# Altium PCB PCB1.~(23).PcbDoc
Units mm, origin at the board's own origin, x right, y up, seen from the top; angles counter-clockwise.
Board outline 145.29 x 144.91 mm, 2 copper layers (Top Layer, Bottom Layer); 47 components, 43 nets, 244 pads, 0 vias.
Unrouted connection lines stored in the file: 137.
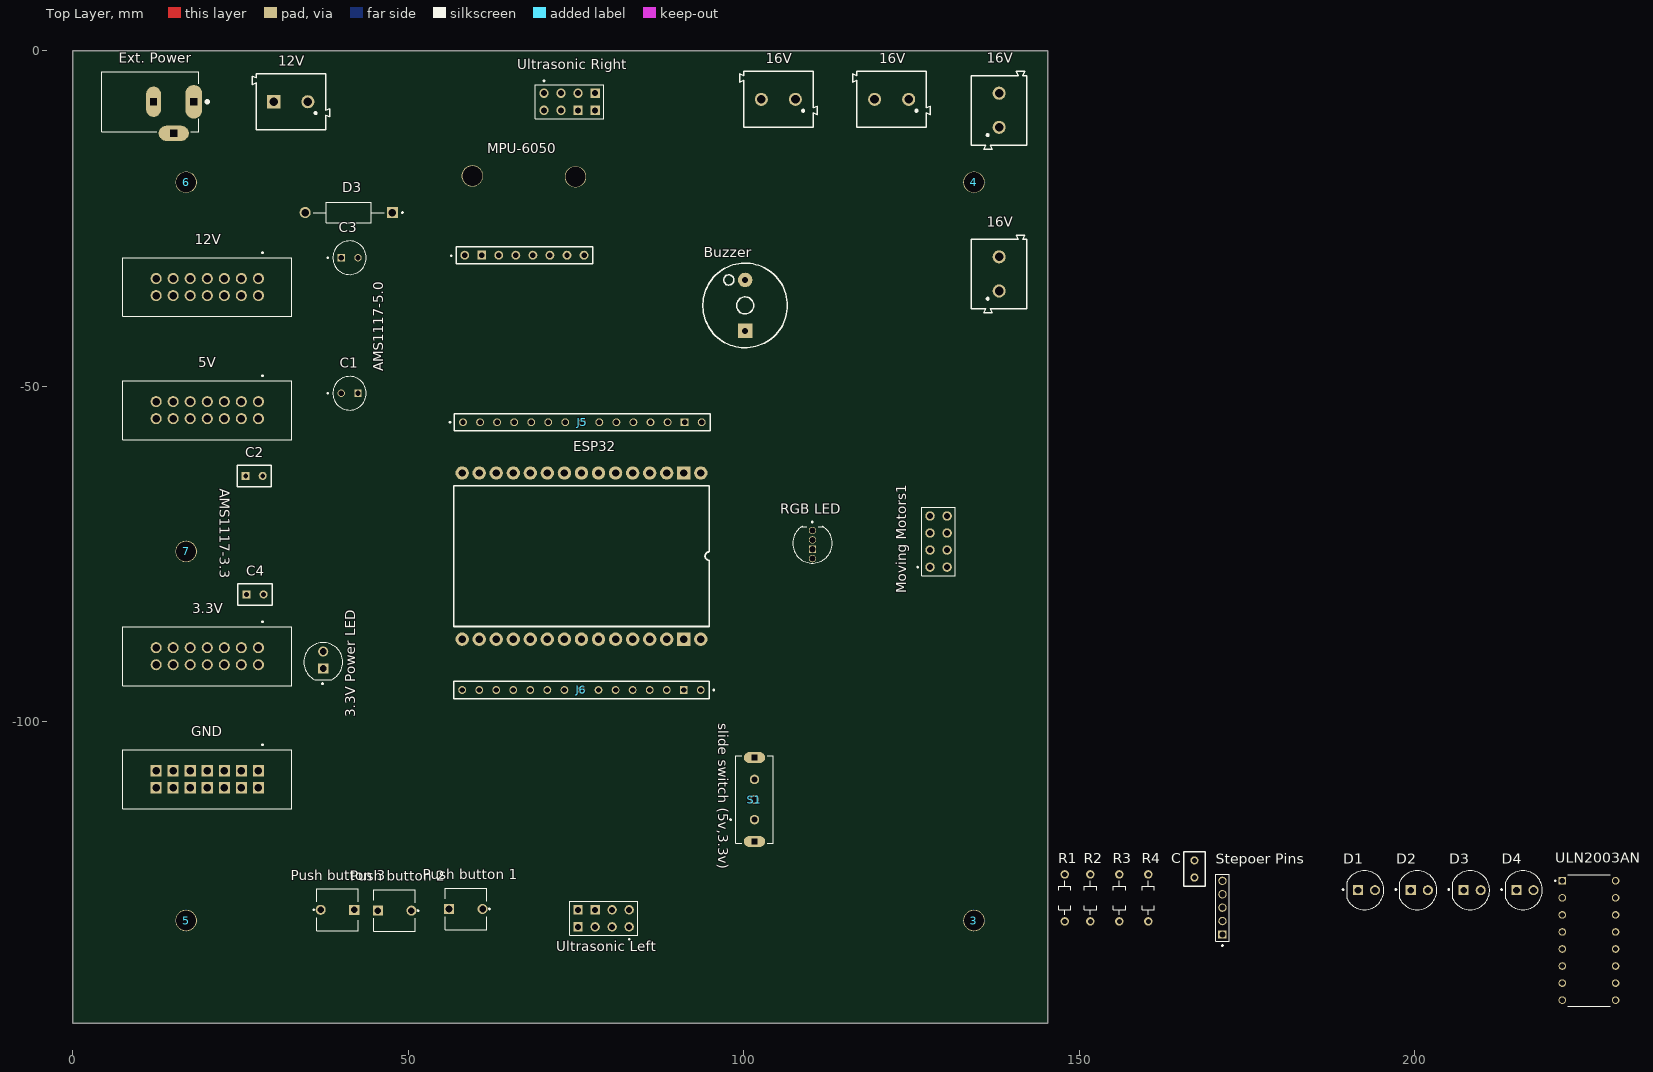
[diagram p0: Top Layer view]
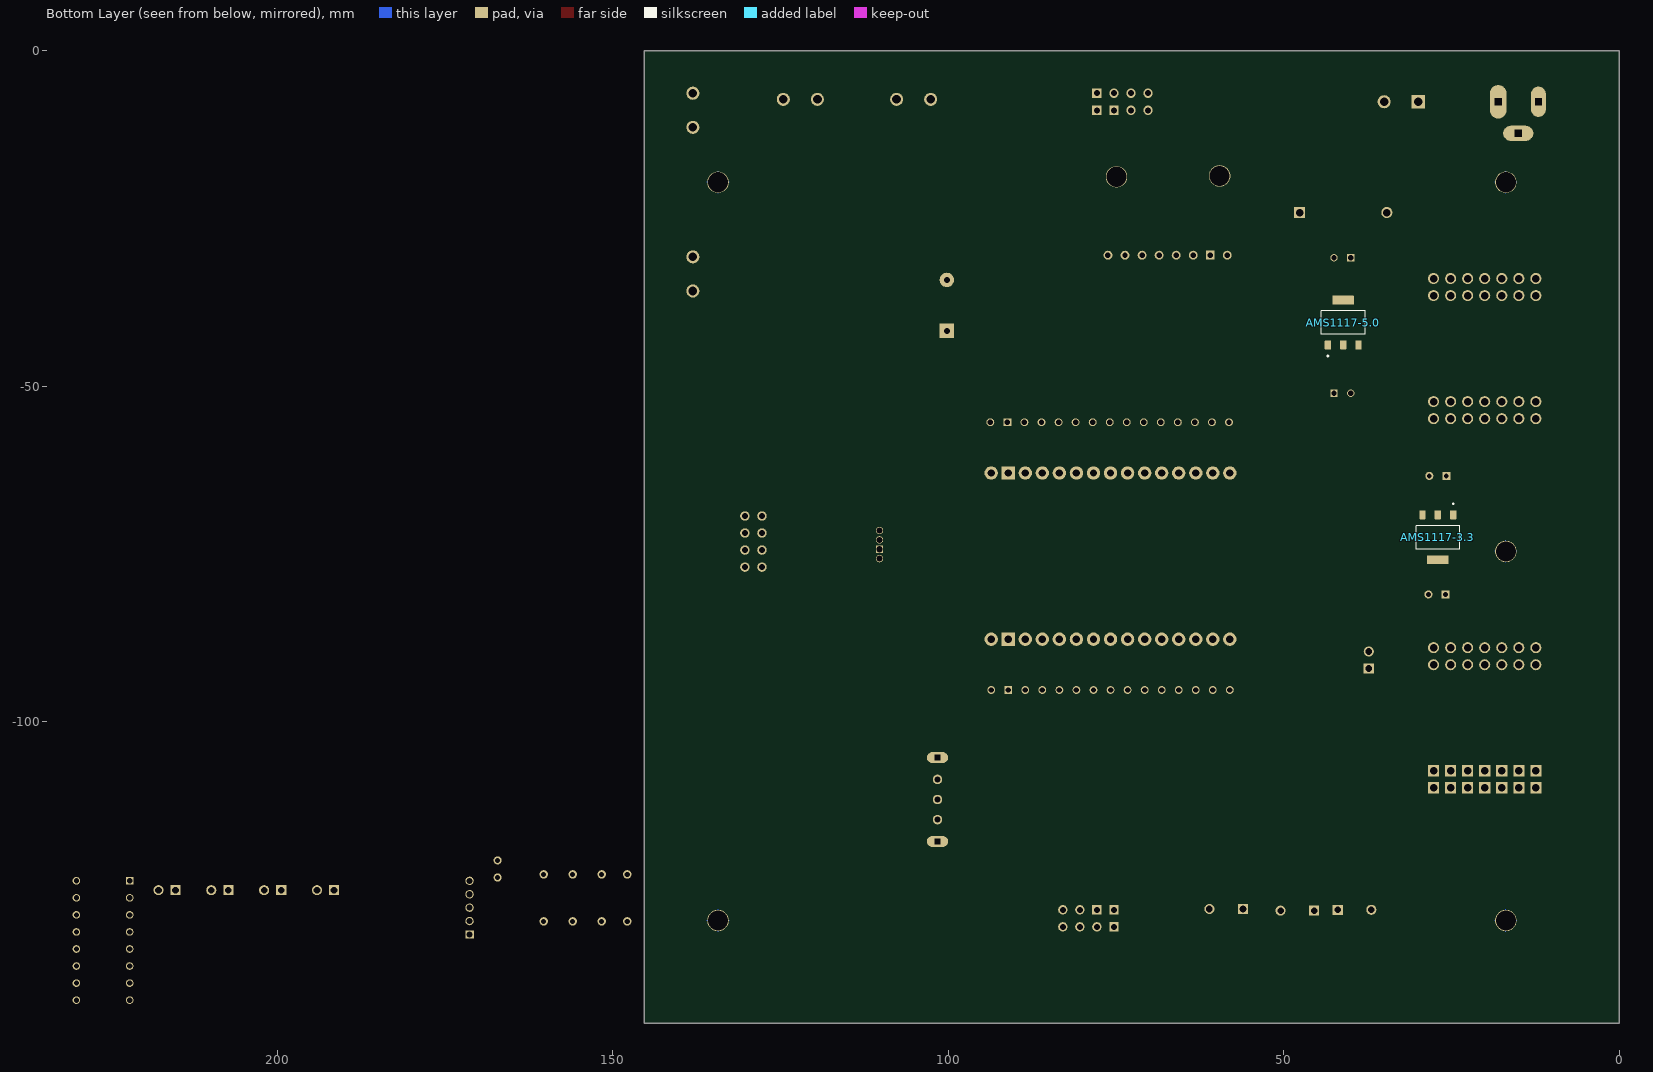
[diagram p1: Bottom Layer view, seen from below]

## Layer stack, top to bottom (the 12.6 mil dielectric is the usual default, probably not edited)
Top Solder: solder mask 0.0102, Solder Resist, Dk 3.5
Top Layer: signal copper 0.0356
Dielectric 1: dielectric 0.32, FR-4, Dk 4.8
Bottom Layer: signal copper 0.0356
Bottom Solder: solder mask 0.0102, Solder Resist, Dk 3.5

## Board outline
0,-144.907 145.288,-144.907 145.288,0 0,0

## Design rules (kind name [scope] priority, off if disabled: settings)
Clearance [All] p1: gap=0.254 ignorepadtopadclearanceinfootprint=FALSE except(0: Arc-Hole Track-Hole SMDPad-Hole THPad-Hole Via-Hole Fill-Hole Poly-Hole Region-Hole Text-Hole; 2: Arc-Poly Track-Poly SMDPad-Poly THPad-Poly)
PolygonConnect [All] p1: connectstyle=Relief reliefconductorwidth=0.254 reliefentries=4 polygonreliefangle="90 Angle" airgapwidth=0.254
RoutingLayers [All] p1: top layer_v5=FALSE bottom layer_v5=TRUE
RoutingVias [All] p1: holewidth=0.711 width=1.27 viastyle="Through Hole" minholewidth=0.711 minwidth=1.27 maxholewidth=0.711 maxwidth=1.27
SolderMaskExpansion [All] p1: expansion=0.102 istentingtop=FALSE
Width [All] p1: maxlimit=0.7 minlimit=0.254 preferedwidth=0.5
29 further rules are at their usual default settings.

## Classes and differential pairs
component class Sheet1: 3 3.3V "3.3V Power LED" 4 5 5V 6 7 12V 16V AMS1117-3.3 AMS1117-5.0 Buzzer C C1 C2 C3 C4 D1 D2 D3 D4 ESP32 "Ext. Power" GND J5 J6 "Moving motors" "Moving Motors1" MPU-6050 "Push button 1" "Push button 2" "Push button 3" R1 R2 R3 R4 "RGB LED" S1 "Stepoer Pins" ULN2003AN "Ultrasonic Left" "Ultrasonic Right"

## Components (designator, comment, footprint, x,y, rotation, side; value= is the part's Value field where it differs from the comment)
3 "Mounting Hole" PCBComponent_1 134.304,-129.619 r90 top
3.3V "3.3v pin headers block" AMPHENOL_52601-S14-4LF#1 20.066,-90.235 r180 top
"3.3V Power LED" "LED 5mm" "LED 5mm" 37.338,-90.805 r90 top
4 "Mounting Hole" PCBComponent_1 134.304,-19.619 r90 top
5 "Mounting Hole" PCBComponent_1 16.916,-129.619 r90 top
5V "5v pin headers block" AMPHENOL_52601-S14-4LF#1 20.066,-53.568 r180 top
6 "Mounting Hole" PCBComponent_1 16.916,-19.619 r90 top
7 "Mounting Hole" PCBComponent_1 16.916,-74.619 r90 top
12V "12v pin headers block" AMPHENOL_52601-S14-4LF#1 20.066,-35.235 r180 top
12V "From Buck" 691213510002#1 32.512,-7.62 r180 top
16V "From Buck" 691213510002#2 138.049,-8.89 r90 top
16V "From Buck" 691213510002#2 138.049,-33.274 r90 top
16V "From Buck" 691213510002#2 122.036,-7.26 r180 top
16V "From Buck" 691213510002#2 105.156,-7.26 r180 top
AMS1117-3.3 "AMS1117-3.3" SOT229P700X180-4N 27.051,-72.517 r270 bottom
AMS1117-5.0 "AMS1117-5.0" SOT229P700X180-4N 41.148,-40.513 r90 bottom
Buzzer "Buzzer" "Buzzer 5V" 100.203,-37.973 r90 top
C "Ceramic Capacitor 100nF" C320C#1 160.147,-114.935 r90 top
C1 "CAP  33UF 50V RADIAL" "CAP  33UF 50V RADIAL"#1 41.275,-51.054 r0 top
C2 "Ceramic Capacitor 100nF" C320C#2 34.051,-56.373 r0 top
C3 "CAP  33UF 50V RADIAL" "CAP  33UF 50V RADIAL"#2 41.275,-30.861 r0 top
C4 "Ceramic Capacitor 100nF" C320C#2 34.178,-74.026 r0 top
D1 "LED 5mm" "LED 5mm" 192.786,-125.095 r0 top
D2 "LED 5mm" "LED 5mm" 200.66,-125.095 r0 top
D3 "LED 5mm" "LED 5mm" 208.534,-125.095 r0 top
D3 "RL207" DIOAD1300W80L670D310 41.148,-24.13 r180 top
D4 "LED 5mm" "LED 5mm" 216.408,-125.095 r0 top
ESP32 "ESP32DEVKITV1" ESP32DEVKITV1 75.946,-74.619 r90 top
"Ext. Power" "DC Power Jack Female Socket" "DC Power Jack Female Socket" 18.065,-7.62 r180 top
GND "GND pin headers block" AMPHENOL_52601-S14-4LF#2 20.066,-108.568 r180 top
J5 "TS-115-T-A-1" SAMTEC_TS-115-T-A-1#1 75.946,-55.372 r0 top
J6 "TS-115-T-A-1" SAMTEC_TS-115-T-A-1#2 75.819,-95.268 r180 top
"Moving Motors1" "Pin header female block 8 pin" "Pin header female block 8 pin"#1 129.032,-73.152 r90 top (schematic designator "Moving motors1")
MPU-6050 "MPU-6050" MPU-6050 56.896,-32.004 r90 top
"Push button 1" "FSM8JRT" TE_FSM8JRT 61.087,-127.889 r180 top
"Push button 2" "FSM8JRT" TE_FSM8JRT 50.482,-128.143 r180 top
"Push button 3" "FSM8JRT" TE_FSM8JRT 36.957,-128.016 r0 top
R1 "Resistor" RESAD700W45L350D185 147.828,-126.238 r90 top
R2 "Resistor" RESAD700W45L350D185 151.638,-126.238 r90 top
R3 "Resistor" RESAD700W45L350D185 155.956,-126.238 r90 top
R4 "Resistor" RESAD700W45L350D185 160.274,-126.238 r90 top
"RGB LED" "common cathode" "LED RGB 5mm" 110.236,-73.406 r270 top
S1 "slide switch (5v,3.3v)" "Slide switch" 101.6,-111.585 r90 top
"Stepoer Pins" "Pin hreader 5 pins" "Pin hreader 5 pins" 171.323,-131.699 r90 top
ULN2003AN "ULN2003AN" DIP794W45P254L1969H508Q16 225.933,-132.588 r0 top
"Ultrasonic Left" "Pin header female block 8 pin" "Pin header female block 8 pin"#2 79.121,-129.286 r180 top
"Ultrasonic Right" "Pin header female block 8 pin" "Pin header female block 8 pin"#2 74.041,-7.62 r0 top

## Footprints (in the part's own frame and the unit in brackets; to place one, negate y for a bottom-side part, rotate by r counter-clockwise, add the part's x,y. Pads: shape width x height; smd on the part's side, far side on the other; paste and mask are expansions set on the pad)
691213510002#1 [mm]
  round 1.95 hole 1.3: 1(-2.54,0)
  rect 1.95x1.95 hole 1.3: 2(2.54,0)
  silkscreen extent -5.78,-4.15 5.78,4.15, body extent -5.68,-3.94 5.68,4.16, height 10
691213510002#2 [mm]
  round 1.95 hole 1.3: 1(-2.54,0) 2(2.54,0)
  silkscreen extent -5.78,-4.15 5.78,4.15, body extent -5.68,-3.94 5.68,4.16, height 10
AMPHENOL_52601-S14-4LF#1 [mm]
  round 1.65 hole 1.1: 1(-7.62,-1.27) 2(-7.62,1.27) 3(-5.08,-1.27) 4(-5.08,1.27) 5(-2.54,-1.27) 6(-2.54,1.27) 7(0,-1.27) 8(0,1.27) 9(2.54,-1.27) 10(2.54,1.27) 11(5.08,-1.27) 12(5.08,1.27) 13(7.62,-1.27) 14(7.62,1.27)
  silkscreen extent -12.57,-5.23 12.57,4.38, body extent -12.57,-4.38 12.57,4.38, height 9.53
AMPHENOL_52601-S14-4LF#2 [mm]
  rect 1.65x1.65 hole 1.1: 1(-7.62,-1.27) 2(-7.62,1.27) 3(-5.08,-1.27) 4(-5.08,1.27) 5(-2.54,-1.27) 6(-2.54,1.27) 7(0,-1.27) 8(0,1.27) 9(2.54,-1.27) 10(2.54,1.27) 11(5.08,-1.27) 12(5.08,1.27) 13(7.62,-1.27) 14(7.62,1.27)
  silkscreen extent -12.57,-5.23 12.57,4.38, body extent -12.57,-4.38 12.57,4.38, height 9.53
"Buzzer 5V" [mil]
  rect 85x85 hole 36: NEG(-149.61,0)
  round 85 hole 36: POS(149.61,0)
  silkscreen extent -248,-248 248,248, body extent -236,-236 236,236, height 394
C320C#1 [mm]
  round 1.21 hole 0.71: 1(-8.27,-7) 2(-5.73,-7)
  silkscreen extent -9.54,-8.59 -4.46,-5.41, body extent -9.53,-8.57 -4.45,-5.4, height 7.1
C320C#2 [mm]
  rect 1.21x1.21 hole 0.71: 1(-8.27,-7)
  round 1.21 hole 0.71: 2(-5.73,-7)
  silkscreen extent -9.54,-8.59 -4.46,-5.41, body extent -9.53,-8.57 -4.45,-5.4, height 7.1
"CAP  33UF 50V RADIAL"#1 [mm]
  rect 1.1x1.1 hole 0.75: N(1.25,0)
  round 1.1 hole 0.75: P(-1.25,0)
  silkscreen extent -3.35,-2.5 2.5,2.5, body extent -2.49,-2.5 2.5,2.5, height 11
"CAP  33UF 50V RADIAL"#2 [mm]
  round 1.1 hole 0.75: N(1.25,0)
  rect 1.1x1.1 hole 0.75: P(-1.25,0)
  silkscreen extent -3.35,-2.5 2.5,2.5, body extent -2.49,-2.5 2.5,2.5, height 11
"DC Power Jack Female Socket" [mm]
  oval 2.5x5 hole 1 square: 1(0,0)
  oval 2.25x4.5 hole 1 square: 2(6,0)
  oval 4.5x2.25 hole 1 square: 3(3,4.7)
  silkscreen extent -2.2,-4.5 13.7,4.5, body extent -0.7,-4.5 13.7,4.9, height 11
DIOAD1300W80L670D310 [mm]
  round 1.65 hole 1.1: A(6.5,0)
  rect 1.65x1.65 hole 1.1: C(-6.5,0)
  silkscreen extent -8.1,-1.55 5.32,1.55, body extent -6.9,-1.95 6.9,1.65, height 3.6
DIP794W45P254L1969H508Q16 [mm]
  rect 1.13x1.13 hole 0.78: 1(-3.97,8.89)
  round 1.13 hole 0.78: 2(-3.97,6.35) 3(-3.97,3.81) 4(-3.97,1.27) 5(-3.97,-1.27) 6(-3.97,-3.81) 7(-3.97,-6.35) 8(-3.97,-8.89) 9(3.97,-8.89) 10(3.97,-6.35) 11(3.97,-3.81) 12(3.97,-1.27) 13(3.97,1.27) 14(3.97,3.81) 15(3.97,6.35) 16(3.97,8.89)
  silkscreen extent -5.13,-9.77 3.17,9.77, body extent -3.95,-10.54 3.95,10.79, height 5.08
ESP32DEVKITV1 [mm]
  round 2 hole 1.1: 1(11.684,-17.653) 3(11.684,-12.573) 4(11.684,-10.033) 5(11.684,-7.493) 6(11.684,-4.953) 7(11.684,-2.413) 8(11.684,0.127) 9(11.684,2.667) 10(11.684,5.207) 11(11.684,7.747) 12(11.684,10.287) 13(11.684,12.827) 14(11.684,15.367) 15(11.684,17.907) 16(-13.086,17.907) 17(-13.086,15.367) 18(-13.086,12.827) 19(-13.086,10.287) 20(-13.086,7.747) 21(-13.086,5.207) 22(-13.086,2.667) 23(-13.086,0.127) 24(-13.086,-2.413) 25(-13.086,-4.953) 26(-13.086,-7.493) 27(-13.086,-10.033) 28(-13.086,-12.573) 30(-13.086,-17.653)
  rect 2x2 hole 1.1: 2(11.684,-15.113) 29(-13.086,-15.113)
  silkscreen extent -11.2,-18.92 9.79,19.18, body extent -15.13,-28.49 13.86,24.48, height 8.36
"LED 5mm" [mm]
  round 1.508 hole 1: A(1.27,0)
  rect 1.508x1.508 hole 1: C(-1.27,0)
  silkscreen extent -3.6,-2.9 2.6,2.9, body extent -2.88,-2.9 2.51,2.9, height 12.1
"LED RGB 5mm" [mm]
  round 1.1 hole 0.9: 1(-1.905,0) 2(-0.508,0) 4(2.286,0)
  rect 1.1x1.1 hole 0.9: 3(0.889,0)
  silkscreen extent -3.27,-2.95 2.95,2.95, body extent -2.47,-3.05 2.98,2.84, height 9.6
MPU-6050 [mil]
  round 52 hole 32: 01(60,-60) 03(60,-260) 04(60,-360) 05(60,-460) 06(60,-560) 07(60,-660) 08(60,-760)
  rect 52x52 hole 32: 02(60,-160)
  round 125.98 hole 118.11: ""(520,-710) ""(525,-105)
  silkscreen extent 10,-810 110,23, body extent 15,-811 615,-9, height 612
PCBComponent_1 [mm]
  round 3.2 hole 3: ""(0,0)
  Bottom Layer lines w0.15: 0,1.649 0,-1.651 ; -1.651,0 1.649,0
"Pin header female block 8 pin"#1 [mm]
  round 1.398 hole 0.89: 1(-3.81,1.27) 2(-1.27,1.27) 3(1.27,1.27) 4(3.81,1.27) 5(-3.81,-1.27) 6(-1.27,-1.27) 7(1.27,-1.27) 8(3.81,-1.27)
  silkscreen extent -5.08,-2.52 5.08,3.21, body extent -5.08,-2.51 5.08,2.51, height 6.22
"Pin header female block 8 pin"#2 [mm]
  round 1.398 hole 0.89: 1(-3.81,1.27) 2(-1.27,1.27) 3(1.27,1.27) 5(-3.81,-1.27) 6(-1.27,-1.27)
  rect 1.398x1.398 hole 0.89: 4(3.81,1.27) 7(1.27,-1.27) 8(3.81,-1.27)
  silkscreen extent -5.08,-2.52 5.08,3.21, body extent -5.08,-2.51 5.08,2.51, height 6.22
"Pin hreader 5 pins" [mm]
  rect 1.25x1.25 hole 0.9: 1(0,0)
  round 1.25 hole 0.9: 2(2,0) 3(4,0) 4(6,0) 5(8,0)
  silkscreen extent -1.75,-1 9,1, body extent -1,-1 9,1, height 5.65
RESAD700W45L350D185 [mm]
  round 1.258 hole 0.75: 1(-3.5,0) 2(3.5,0)
  silkscreen extent -2.55,-0.92 2.55,0.92, body extent -3.72,-1.05 3.72,0.8, height 1.85
SAMTEC_TS-115-T-A-1#1 [mil]
  round 45.78 hole 32: 01(-700,0) 02(-600,0) 03(-500,0) 04(-400,0) 05(-300,0) 06(-200,0) 07(-100,0) 08(0,0) 09(100,0) 10(200,0) 11(300,0) 12(400,0) 13(500,0) 15(700,0)
  rect 45.78x45.78 hole 32: 14(600,0)
  silkscreen extent -780,-50 750,50, body extent -754,-50 754,50, height 326
SAMTEC_TS-115-T-A-1#2 [mil]
  round 45.78 hole 32: 01(-700,0) 03(-500,0) 04(-400,0) 05(-300,0) 06(-200,0) 07(-100,0) 08(0,0) 09(100,0) 10(200,0) 11(300,0) 12(400,0) 13(500,0) 14(600,0) 15(700,0)
  rect 45.78x45.78 hole 32: 02(-600,0)
  silkscreen extent -780,-50 750,50, body extent -754,-50 754,50, height 326
"Slide switch" [mm]
  round 1.408 hole 0.9: 1(-3,0) 2(0,0) 3(3,0)
  oval 1.6x3.2 hole 0.8 square: SH1(-6.25,0) SH2(6.25,0)
  silkscreen extent -6.5,-2.8 6.5,3.66, body extent -6.5,-5.8 6.5,2.8, height 6
SOT229P700X180-4N [mm]
  rrect15% 1.31x0.93 smd: 1(-3.345,2.29) 2(-3.345,0) 3(-3.345,-2.29)
  rrect15% 1.31x3.24 smd: 4(3.345,0)
  silkscreen extent -5.1,-3.25 1.75,3.25, body extent -3.5,-3.25 3.5,3.25, height 1.8
TE_FSM8JRT [mil]
  round 59 hole 39: 1(0,0)
  rect 59x59 hole 39: 2(197,0)
  silkscreen extent -44,-122 221,122, body extent -22,-122 222,122, height 372

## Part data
3.3V 5V 12V GND: library part 52601-S14-4LF, Package=None
"3.3V Power LED" D1 D2 D3 D4: "Red 623nm LED Indication - Discrete 1.9V Radial", Package=None
12V 16V 16V 16V 16V: library part "Terminal Block", "2 Position Wire to Board Terminal Block Horizontal with Board 0.200 (5.08mm) Through Hole", Package=None
AMS1117-3.3 AMS1117-5.0 J5 J6 "Moving Motors1" "Stepoer Pins" ULN2003AN "Ultrasonic Left" "Ultrasonic Right": Package=None
Buzzer: library part "Buzzer 5V", "BUZZER 2.3KHZ 4-6VDC", Package=None
C C2 C4: "0.1ÂµF Â±20% 50V Ceramic Capacitor Z5U Radial", Package="Radial KEMET"
C1 C3: "NHG-A", Package=None
D3: "Semiconductors and Actives, Power Diodes, Discretes (diodes, transistors, thyristors ...), Diodes", Package=None
"Ext. Power": "2.0 mm Center Pin, 2.5 A, Right Angle, Through Hole, Dc Power Jack Connector", Package=None
"Push button 1" "Push button 2" "Push button 3": "Tactile Switches PUSHBUTTON SWITCH TACT", Package=None
R1 R2 R3 R4: "CFR16 5% 10K", Package=None
"RGB LED": library part "LED RGB 5mm", Package=None
S1: library part "Slide switch", Package=None

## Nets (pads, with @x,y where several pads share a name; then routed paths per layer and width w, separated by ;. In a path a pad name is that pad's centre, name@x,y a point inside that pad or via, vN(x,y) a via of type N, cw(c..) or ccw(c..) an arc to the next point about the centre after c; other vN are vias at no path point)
3.3V: 3.3V.1 3.3V.2 3.3V.3 3.3V.4 3.3V.5 3.3V.6 3.3V.7 3.3V.8 3.3V.9 3.3V.10 3.3V.11 3.3V.12 3.3V.13 3.3V.14 AMS1117-3.3.2 C2.2 ESP32.1 J5.15 MPU-6050.01
+5: 5V.1 5V.2 5V.3 5V.4 5V.5 5V.6 5V.7 5V.8 5V.9 5V.10 5V.11 5V.12 5V.13 5V.14 "Ultrasonic Left.1" "Ultrasonic Left.5" "Ultrasonic Right.1" "Ultrasonic Right.5" AMS1117-5.0.2 C1.P S1.2
+12: 12V.1 12V.2@27.686,-36.505 12V.3 12V.4 12V.5 12V.6 12V.7 12V.8 12V.9 12V.10 12V.11 12V.12 12V.13 12V.14 "Ext. Power.1" "Stepoer Pins.1" C.1 D1.A D2.A D3.A D4.A ULN2003AN.9
GND: 12V.2@29.972,-7.62 "3.3V Power LED.C" "Ext. Power.2" "Ext. Power.3" "Push button 1.2" "Push button 2.2" "Push button 3.2" "RGB LED.3" "Ultrasonic Left.4" "Ultrasonic Left.7" "Ultrasonic Left.8" "Ultrasonic Right.4" "Ultrasonic Right.7" "Ultrasonic Right.8" AMS1117-3.3.1 AMS1117-5.0.1 Buzzer.NEG C1.N C2.1 C3.N C4.1 C.2 ESP32.2 ESP32.29 GND.1 GND.2 GND.3 GND.4 GND.5 GND.6 GND.7 GND.8 GND.9 GND.10 GND.11 GND.12 GND.13 GND.14 J5.14 J6.02 MPU-6050.02 ULN2003AN.8 ULN2003AN.10 ULN2003AN.11 ULN2003AN.12
"Net3.3V Power LED_A": "3.3V Power LED.A" AMS1117-3.3.3 C4.2 S1.3
Net16V_1: 16V.1
Net16V_2: 16V.2
NetAMS1117-5.0_3: AMS1117-5.0.3 C3.P D3.C@47.648,-24.13
NetBuzzer_POS: Buzzer.POS ESP32.15 J5.01
NetD1_C: D1.C R1.2
NetD2_C: D2.C R2.2
NetD3_C: D3.C@207.264,-125.095 R3.2
NetD4_C: D4.C R4.2
NetESP32_3: "Moving Motors1.8" ESP32.3 J5.13
NetESP32_4: "Moving Motors1.7" ESP32.4 J5.12
NetESP32_5: "Moving Motors1.6" ESP32.5 J5.11
NetESP32_6: ESP32.6 J5.10 ULN2003AN.4
NetESP32_7: ESP32.7 J5.09 ULN2003AN.3
NetESP32_8: "Ultrasonic Right.2" ESP32.8 J5.08
NetESP32_9: "Ultrasonic Right.3" ESP32.9 J5.07
NetESP32_10: "Ultrasonic Right.6" ESP32.10 J5.06
NetESP32_11: ESP32.11 J5.05 MPU-6050.04
NetESP32_12: "RGB LED.2" ESP32.12 J5.04
NetESP32_13: "RGB LED.1" ESP32.13 J5.03
NetESP32_14: ESP32.14 J5.02 MPU-6050.03
NetESP32_16: ESP32.16 J6.15
NetESP32_17: "Push button 3.1" ESP32.17 J6.14
NetESP32_18: "Push button 2.1" ESP32.18 J6.13
NetESP32_19: "Push button 1.1" ESP32.19 J6.12
NetESP32_20: "Ultrasonic Left.3" ESP32.20 J6.11
NetESP32_21: "Ultrasonic Left.2" ESP32.21 J6.10
NetESP32_22: "Ultrasonic Left.6" ESP32.22 J6.09
NetESP32_23: "RGB LED.4" ESP32.23 J6.08
NetESP32_24: ESP32.24 J6.07 ULN2003AN.2
NetESP32_25: ESP32.25 J6.06 ULN2003AN.1
NetESP32_26: "Moving Motors1.2" ESP32.26 J6.05
NetESP32_27: "Moving Motors1.3" ESP32.27 J6.04
NetESP32_28: "Moving Motors1.1" ESP32.28 J6.03
NetESP32_30: ESP32.30 J6.01 S1.1
NetR1_1: "Stepoer Pins.5" R1.1 ULN2003AN.13
NetR2_1: "Stepoer Pins.4" R2.1 ULN2003AN.14
NetR3_1: "Stepoer Pins.3" R3.1 ULN2003AN.15
NetR4_1: "Stepoer Pins.2" R4.1 ULN2003AN.16
pads on no net: 3. 4. 5. 6. 7. "Moving Motors1.4" "Moving Motors1.5" AMS1117-3.3.4 AMS1117-5.0.4 MPU-6050. MPU-6050.05 MPU-6050.06 MPU-6050.07 MPU-6050.08 S1.SH1 S1.SH2 ULN2003AN.5 ULN2003AN.6 ULN2003AN.7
